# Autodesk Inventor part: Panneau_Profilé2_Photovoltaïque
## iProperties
Created: 2009-02
Part Number: Panneau_Profilé2_Photovoltaïque
Document SubType Name: Modeling
Designer: claivier
Author: claivier
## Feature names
1. Extrusion1
2. Perçage1 [Hole]
3. Extrusion3
4. Perçage2 [Hole]
5. Perçage3 [Hole]
